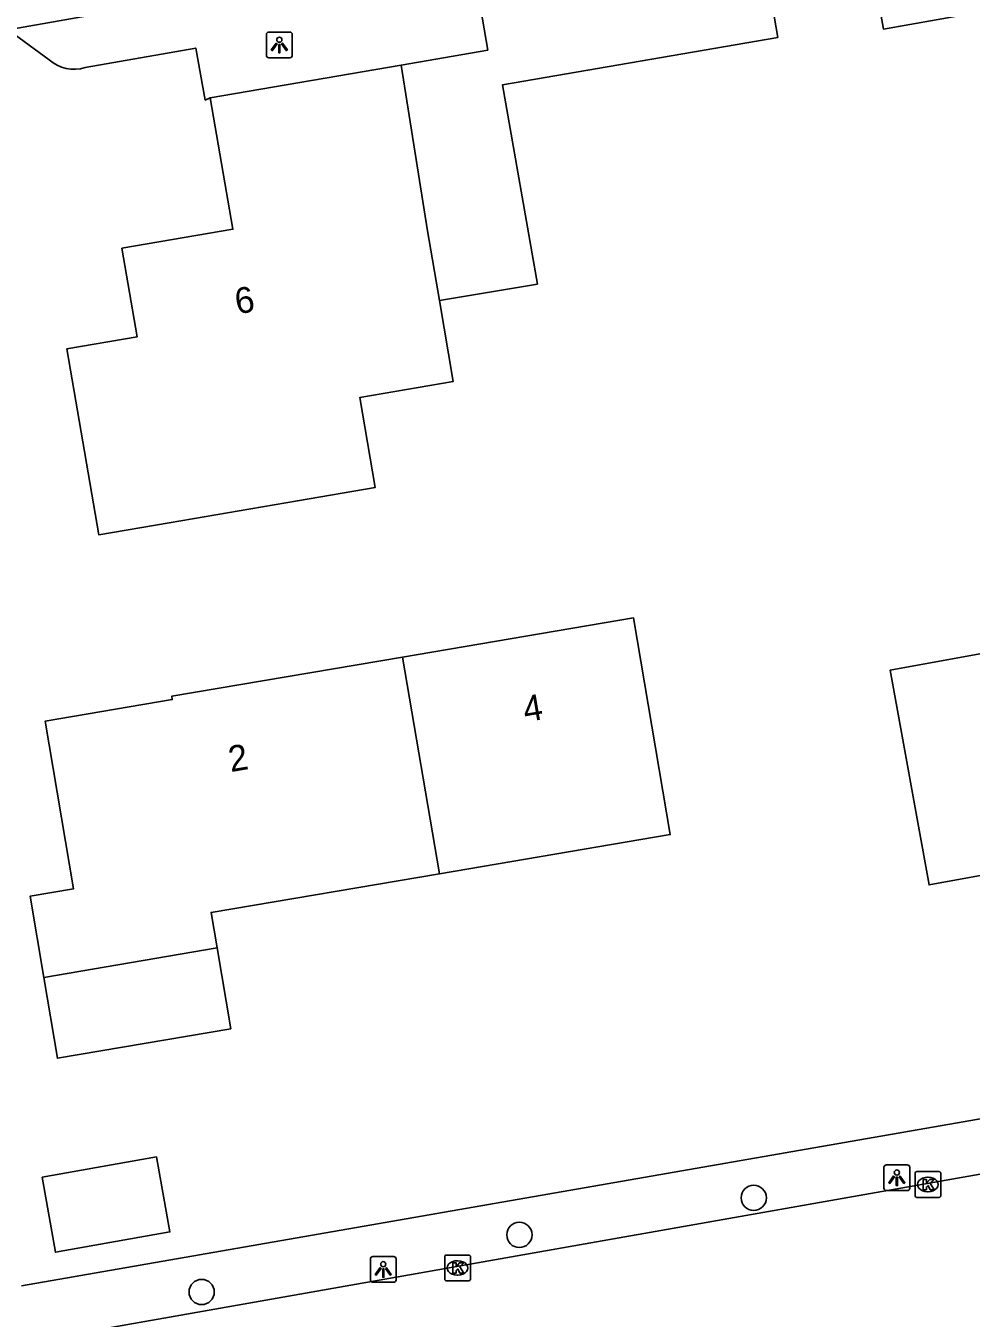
# Model space of a CAD drawing. Extents: x 162880 to 165536, y 384011 to 385179.
# Drawn here: x 163920.7 to 163957.3, y 384694 to 384744.1 of the extents above; entities that cross this region are included whole.
import ezdxf

# ---------------------------------------------------------------- set-up
doc = ezdxf.new("R2010")
doc.units = 0
for name, color, linetype in [('IMGEO_Boom', 7, 'Continuous'), ('IMGEO_Kolk', 7, 'Continuous'), ('IMGEO_Lichtpunt', 7, 'Continuous'), ('IMGEO_Pand', 7, 'Continuous'), ('IMGEO_Pand_nummerreeks', 7, 'Continuous'), ('IMGEO_Rijbaan_lokaal_gesloten', 7, 'Continuous'), ('IMGEO_Rijbaan_lokaal_open', 7, 'Continuous'), ('IMGEO_Voetpad_open', 7, 'Continuous')]:
    doc.layers.add(name, color=color, linetype=linetype)

msp = doc.modelspace()

# ---------------------------------------------------------------- linework, layer by layer
at = {"layer": 'IMGEO_Boom'}
for centre in [(163948.907, 384698.685), (163939.831, 384697.251), (163927.526, 384695.039)]:
    msp.add_circle(centre, 0.489, dxfattribs=at)
at = {"layer": 'IMGEO_Kolk'}
for p, q in [((163955.154, 384698.775), (163955.154, 384699.627)), ((163955.229, 384699.701), (163956.081, 384699.701)), ((163955.642, 384699.481), (163955.667, 384699.481)), ((163956.155, 384699.627), (163956.155, 384698.775)), ((163955.665, 384698.921), (163955.64, 384698.921)), ((163956.081, 384698.701), (163955.229, 384698.701)), ((163936.937, 384695.543), (163936.937, 384696.395)), ((163937.012, 384696.469), (163937.864, 384696.469)), ((163937.938, 384696.395), (163937.938, 384695.543)), ((163937.425, 384696.249), (163937.45, 384696.249)), ((163937.864, 384695.469), (163937.012, 384695.469)), ((163937.448, 384695.689), (163937.423, 384695.689))]:
    msp.add_line(p, q, dxfattribs=at)
for points in [[(163955.154, 384698.775), (163955.154, 384699.627)], [(163955.229, 384699.701), (163956.081, 384699.701)], [(163955.475, 384699.401), (163955.598, 384699.401), (163955.598, 384699.25), (163955.728, 384699.401), (163955.892, 384699.401), (163955.746, 384699.25), (163955.899, 384699.001), (163955.747, 384699.001), (163955.662, 384699.165), (163955.598, 384699.098), (163955.598, 384699.001), (163955.475, 384699.001), (163955.475, 384699.401)], [(163956.155, 384699.627), (163956.155, 384698.775)], [(163956.081, 384698.701), (163955.229, 384698.701)], [(163936.937, 384695.543), (163936.937, 384696.395)], [(163937.012, 384696.469), (163937.864, 384696.469)], [(163937.938, 384696.395), (163937.938, 384695.543)], [(163937.258, 384696.169), (163937.381, 384696.169), (163937.381, 384696.018), (163937.511, 384696.169), (163937.675, 384696.169), (163937.529, 384696.018), (163937.682, 384695.769), (163937.53, 384695.769), (163937.445, 384695.933), (163937.381, 384695.866), (163937.381, 384695.769), (163937.258, 384695.769), (163937.258, 384696.169)], [(163937.864, 384695.469), (163937.012, 384695.469)]]:
    msp.add_lwpolyline(points, dxfattribs=at)
for centre, start, end in [((163955.231, 384699.625), 91.552, 178.448), ((163955.231, 384699.625), 91.552, 178.448), ((163956.079, 384699.625), 1.552, 88.448), ((163956.079, 384699.625), 1.552, 88.448), ((163955.231, 384698.777), 181.552, 268.448), ((163955.231, 384698.777), 181.552, 268.448), ((163956.079, 384698.777), 271.552, 358.448), ((163956.079, 384698.777), 271.552, 358.448), ((163937.014, 384696.393), 91.552, 178.448), ((163937.014, 384696.393), 91.552, 178.448), ((163937.862, 384696.393), 1.552, 88.448), ((163937.862, 384696.393), 1.552, 88.448), ((163937.014, 384695.545), 181.552, 268.448), ((163937.014, 384695.545), 181.552, 268.448), ((163937.862, 384695.545), 271.552, 358.448), ((163937.862, 384695.545), 271.552, 358.448)]:
    msp.add_arc(centre, 0.0765, start, end, dxfattribs=at)
for centre, major_axis, ratio, start_param, end_param in [((163955.641, 384699.201), (-0.387, 0.002), 0.722429, 4.712389, 7.853982), ((163955.666, 384699.201), (-0.39, 0.002), 0.717154, 1.570796, 4.712389), ((163937.424, 384695.969), (-0.387, 0.002), 0.722429, 4.712389, 7.853982), ((163937.449, 384695.969), (-0.39, 0.002), 0.717154, 1.570796, 4.712389)]:
    msp.add_ellipse(centre, major_axis=major_axis, ratio=ratio, start_param=start_param, end_param=end_param, dxfattribs=at)
at = {"layer": 'IMGEO_Lichtpunt'}
for p, q in [((163930.937, 384743.82), (163930.129, 384743.82)), ((163930.937, 384743.82), (163930.129, 384743.82)), ((163930.035, 384743.725), (163930.035, 384742.918)), ((163930.035, 384743.725), (163930.035, 384742.918)), ((163931.031, 384742.918), (163931.031, 384743.725)), ((163931.031, 384742.918), (163931.031, 384743.725)), ((163930.129, 384742.824), (163930.937, 384742.824)), ((163930.129, 384742.824), (163930.937, 384742.824)), ((163953.953, 384699.867), (163953.953, 384699.06)), ((163953.953, 384699.867), (163953.953, 384699.06)), ((163954.855, 384699.962), (163954.047, 384699.962)), ((163954.855, 384699.962), (163954.047, 384699.962)), ((163954.949, 384699.06), (163954.949, 384699.867)), ((163954.949, 384699.06), (163954.949, 384699.867)), ((163954.047, 384698.966), (163954.855, 384698.966)), ((163954.047, 384698.966), (163954.855, 384698.966)), ((163934.06, 384696.318), (163934.06, 384695.511)), ((163934.06, 384696.318), (163934.06, 384695.511)), ((163934.962, 384696.413), (163934.154, 384696.413)), ((163934.962, 384696.413), (163934.154, 384696.413)), ((163935.056, 384695.511), (163935.056, 384696.318)), ((163935.056, 384695.511), (163935.056, 384696.318)), ((163934.154, 384695.417), (163934.962, 384695.417)), ((163934.154, 384695.417), (163934.962, 384695.417))]:
    msp.add_line(p, q, dxfattribs=at)
for points in [[(163930.409, 384743.389), (163930.448, 384743.361), (163930.26, 384743.099), (163930.222, 384743.126), (163930.409, 384743.389)], [(163930.511, 384743.341), (163930.558, 384743.341), (163930.558, 384743.019), (163930.511, 384743.019), (163930.511, 384743.341)], [(163930.621, 384743.361), (163930.659, 384743.388), (163930.846, 384743.126), (163930.807, 384743.098), (163930.621, 384743.361)], [(163954.327, 384699.531), (163954.366, 384699.503), (163954.178, 384699.241), (163954.14, 384699.268), (163954.327, 384699.531)], [(163954.429, 384699.483), (163954.476, 384699.483), (163954.476, 384699.161), (163954.429, 384699.161), (163954.429, 384699.483)], [(163954.539, 384699.503), (163954.577, 384699.53), (163954.764, 384699.268), (163954.725, 384699.24), (163954.539, 384699.503)], [(163934.434, 384695.982), (163934.473, 384695.954), (163934.285, 384695.692), (163934.247, 384695.719), (163934.434, 384695.982)], [(163934.536, 384695.934), (163934.583, 384695.934), (163934.583, 384695.612), (163934.536, 384695.612), (163934.536, 384695.934)], [(163934.646, 384695.954), (163934.684, 384695.981), (163934.871, 384695.719), (163934.832, 384695.691), (163934.646, 384695.954)]]:
    msp.add_lwpolyline(points, dxfattribs=at)
for centre in [(163930.534, 384743.523), (163954.452, 384699.665), (163934.559, 384696.116)]:
    msp.add_circle(centre, 0.0994, dxfattribs=at)
for centre, start, end in [((163930.129, 384743.725), 90, 180), ((163930.129, 384743.725), 90, 180), ((163930.937, 384743.725), 0, 90), ((163930.937, 384743.725), 0, 90), ((163930.129, 384742.918), 180, 270), ((163930.129, 384742.918), 180, 270), ((163930.937, 384742.918), 270, 0), ((163930.937, 384742.918), 270, 360), ((163954.047, 384699.867), 90, 180), ((163954.047, 384699.867), 90, 180), ((163954.855, 384699.867), 0, 90), ((163954.855, 384699.867), 0, 90), ((163954.047, 384699.06), 180, 270), ((163954.047, 384699.06), 180, 270), ((163954.855, 384699.06), 270, 0), ((163954.855, 384699.06), 270, 360), ((163934.154, 384696.318), 90, 180), ((163934.154, 384696.318), 90, 180), ((163934.962, 384696.318), 0, 90), ((163934.962, 384696.318), 0, 90), ((163934.154, 384695.511), 180, 270), ((163934.154, 384695.511), 180, 270), ((163934.962, 384695.511), 270, 0), ((163934.962, 384695.511), 270, 360)]:
    msp.add_arc(centre, 0.0946, start, end, dxfattribs=at)
at = {"layer": 'IMGEO_Pand'}
for points in [[(163952.738, 384750.674), (163953.931, 384743.934), (163959.034, 384744.838), (163959.873, 384740.096), (163965.714, 384741.069), (163970.387, 384741.829), (163969.029, 384749.504), (163961.369, 384748.149), (163961.061, 384750), (163960.734, 384751.96), (163960.714, 384752.08)], [(163936.733, 384733.425), (163940.532, 384734.062), (163939.177, 384741.782), (163949.839, 384743.614), (163949.338, 384746.539), (163948.743, 384750), (163948.492, 384751.457), (163940.189, 384750), (163937.505, 384749.529), (163937.56, 384749.211)], [(163937.56, 384749.211), (163938.606, 384743.121), (163935.25, 384742.544)], [(163935.25, 384742.544), (163927.86, 384741.275)], [(163936.733, 384733.425), (163936.27, 384736.127), (163935.25, 384742.544)], [(163927.86, 384741.275), (163928.734, 384736.186), (163924.434, 384735.447), (163925.023, 384732.018), (163922.304, 384731.551), (163923.54, 384724.355), (163926.26, 384724.822), (163931.235, 384725.677), (163934.25, 384726.189), (163933.652, 384729.673), (163937.27, 384730.292), (163936.733, 384733.425)], [(163936.731, 384711.232), (163945.677, 384712.747), (163944.256, 384721.137), (163935.31, 384719.622)], [(163963.059, 384720.723), (163954.189, 384719.111), (163955.7, 384710.8), (163964.568, 384712.411)], [(163935.31, 384719.622), (163926.364, 384718.107), (163926.385, 384717.979), (163921.464, 384717.146), (163922.564, 384710.649), (163920.877, 384710.363), (163921.41, 384707.215)], [(163935.31, 384719.622), (163936.731, 384711.232)], [(163928.121, 384708.37), (163927.89, 384709.735), (163936.731, 384711.232)], [(163921.41, 384707.215), (163921.938, 384704.092), (163928.653, 384705.229), (163928.121, 384708.37)], [(163921.41, 384707.215), (163928.121, 384708.37)], [(163921.348, 384699.484), (163925.775, 384700.271), (163926.293, 384697.363), (163921.866, 384696.576), (163921.348, 384699.484)]]:
    msp.add_lwpolyline(points, dxfattribs=at)
at = {"layer": 'IMGEO_Rijbaan_lokaal_gesloten'}
msp.add_lwpolyline([(163920.933, 384693.119), (163986.876, 384704.755)], dxfattribs=at)
at = {"layer": 'IMGEO_Rijbaan_lokaal_open'}
msp.add_lwpolyline([(163919.73, 384743.856), (163927.644, 384745.267), (163930.393, 384745.609), (163929.752, 384750), (163929.624, 384750.664)], dxfattribs=at)
at = {"layer": 'IMGEO_Voetpad_open'}
for points in [[(163919.73, 384743.856), (163920.259, 384743.743), (163921.62, 384742.749)], [(163923.011, 384742.448), (163927.296, 384743.202), (163927.667, 384741.185), (163927.86, 384741.275)], [(163986.591, 384706.78), (163920.553, 384695.282)]]:
    msp.add_lwpolyline(points, dxfattribs=at)
msp.add_arc((163922.571, 384743.779), 1.402, 227.2919, 288.288, dxfattribs=at)

# ---------------------------------------------------------------- texts
at = {"layer": 'IMGEO_Pand_nummerreeks'}
for s, rotation, p in [('6', 9.7517, (163928.9, 384732.888)), ('4', 9.6243, (163940.06, 384717.098)), ('2', 9.6038, (163928.65, 384715.166))]:
    msp.add_text(s, height=1, rotation=rotation, dxfattribs=at).set_placement(p)

doc.saveas('drawing.dxf')
